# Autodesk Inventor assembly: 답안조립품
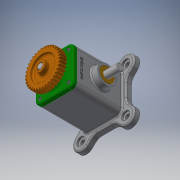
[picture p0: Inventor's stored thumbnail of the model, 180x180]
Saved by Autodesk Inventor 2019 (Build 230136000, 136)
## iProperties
Created: 2021-01
Part Number: 답안조립품
Material: 일반
Document SubType Name: Assembly
Designer: 3dpro12
Author: 3dpro12
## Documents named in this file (11)
- C:\Users\3dpro12\Desktop\710114V1004\710114V1004\답안조립품.iam
- C:\Users\3dpro12\Desktop\710114V1004\710114V1004\본체.ipt
- C:\Users\3dpro12\Desktop\710114V1004\710114V1004\베어링 6203.ipt
- C:\Users\3dpro12\Desktop\710114V1004\710114V1004\볼트 M4.ipt
- C:\Users\3dpro12\Desktop\710114V1004\710114V1004\부시.ipt
- C:\Users\3dpro12\Desktop\710114V1004\710114V1004\스퍼기어.ipt
- C:\Users\3dpro12\Desktop\710114V1004\710114V1004\슬라이더.ipt
- C:\Users\3dpro12\Desktop\710114V1004\710114V1004\오일 실.ipt
- C:\Users\3dpro12\Desktop\710114V1004\710114V1004\커버.ipt
- C:\Users\3dpro12\Desktop\710114V1004\710114V1004\키 4 x 4 x 14.ipt
- C:\Users\3dpro12\Desktop\710114V1004\710114V1004\편심축.ipt
